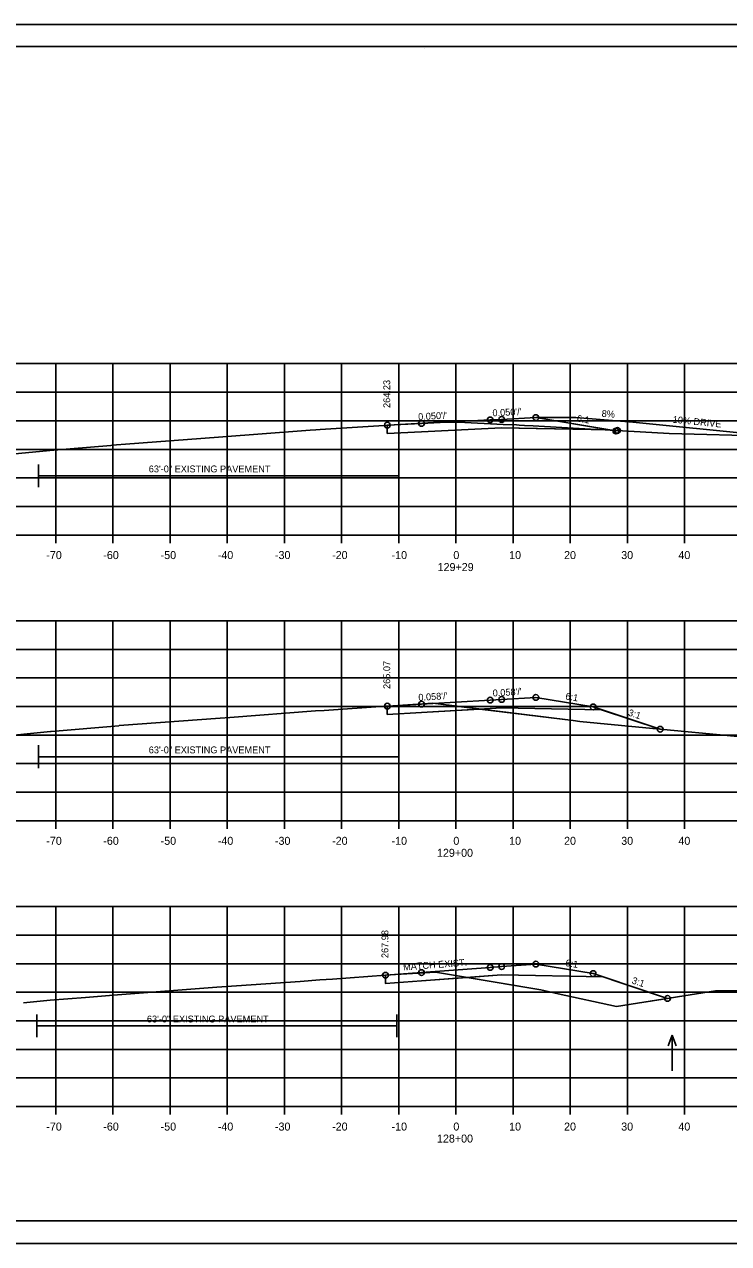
# Model space of a CAD drawing. Extents: x 1103485 to 1107180, y 2010593 to 2011873.
# Drawn here: x 1106941.7 to 1107064.9, y 2011019.5 to 2011232.8 of the extents above; entities that cross this region are included whole.
import ezdxf

# ---------------------------------------------------------------- set-up
doc = ezdxf.new("R2010")
doc.units = 0
for name, color, linetype in [('R_Alt Surface', 7, 'Continuous'), ('R_Axis', 7, 'Continuous'), ('R_Axis Annot', 7, 'Continuous'), ('R_Border', 7, 'Continuous'), ('R_Contours', 7, 'Continuous'), ('R_Dimension', 7, 'Continuous'), ('R_Drive', 7, 'Continuous'), ('R_Exist Surface', 7, 'Continuous'), ('R_Fin Surface', 7, 'Continuous'), ('R_Grid', 7, 'Continuous'), ('R_No Plot', 7, 'Continuous'), ('R_Proposed Const Limits', 7, 'Continuous'), ('R_Water Annot', 7, 'Continuous'), ('R_Xsect Elev', 7, 'Continuous'), ('R_Xsect Slope', 7, 'Continuous')]:
    doc.layers.add(name, color=color, linetype=linetype)

msp = doc.modelspace()

# ---------------------------------------------------------------- linework, layer by layer
at = {"layer": 'R_Alt Surface'}
for points in [[(1107005.18, 2011162.73), (1107005.18, 2011161.27), (1107011.18, 2011161.57), (1107025.18, 2011162.27), (1107044.02, 2011161.9)], [(1107005.18, 2011113.56), (1107005.18, 2011112.1), (1107011.18, 2011112.45), (1107025.18, 2011113.27), (1107042.67, 2011112.92)], [(1107004.86, 2011066.47), (1107004.86, 2011065.01), (1107011.18, 2011065.48), (1107025.18, 2011066.52), (1107042.97, 2011066.17)]]:
    msp.add_lwpolyline(points, dxfattribs=at)
at = {"layer": 'R_Axis'}
for p, q in [((1106867.18, 2011143.49), (1107167.18, 2011143.49)), ((1106947.18, 2011142.09), (1106947.18, 2011143.49)), ((1106957.18, 2011142.09), (1106957.18, 2011143.49)), ((1106967.18, 2011142.09), (1106967.18, 2011143.49)), ((1106977.18, 2011142.09), (1106977.18, 2011143.49)), ((1106987.18, 2011142.09), (1106987.18, 2011143.49)), ((1106997.18, 2011142.09), (1106997.18, 2011143.49)), ((1107007.18, 2011142.09), (1107007.18, 2011143.49)), ((1107017.18, 2011142.09), (1107017.18, 2011143.49)), ((1107027.18, 2011142.09), (1107027.18, 2011143.49)), ((1107037.18, 2011142.09), (1107037.18, 2011143.49)), ((1107047.18, 2011142.09), (1107047.18, 2011143.49)), ((1107057.18, 2011142.09), (1107057.18, 2011143.49)), ((1106867.18, 2011093.49), (1107167.18, 2011093.49)), ((1106947.18, 2011092.09), (1106947.18, 2011093.49)), ((1106957.18, 2011092.09), (1106957.18, 2011093.49)), ((1106967.18, 2011092.09), (1106967.18, 2011093.49)), ((1106977.18, 2011092.09), (1106977.18, 2011093.49)), ((1106987.18, 2011092.09), (1106987.18, 2011093.49)), ((1106997.18, 2011092.09), (1106997.18, 2011093.49)), ((1107007.18, 2011092.09), (1107007.18, 2011093.49)), ((1107017.18, 2011092.09), (1107017.18, 2011093.49)), ((1107027.18, 2011092.09), (1107027.18, 2011093.49)), ((1107037.18, 2011092.09), (1107037.18, 2011093.49)), ((1107047.18, 2011092.09), (1107047.18, 2011093.49)), ((1107057.18, 2011092.09), (1107057.18, 2011093.49)), ((1106867.18, 2011043.49), (1107167.18, 2011043.49)), ((1106947.18, 2011042.09), (1106947.18, 2011043.49)), ((1106957.18, 2011042.09), (1106957.18, 2011043.49)), ((1106967.18, 2011042.09), (1106967.18, 2011043.49)), ((1106977.18, 2011042.09), (1106977.18, 2011043.49)), ((1106987.18, 2011042.09), (1106987.18, 2011043.49)), ((1106997.18, 2011042.09), (1106997.18, 2011043.49)), ((1107007.18, 2011042.09), (1107007.18, 2011043.49)), ((1107017.18, 2011042.09), (1107017.18, 2011043.49)), ((1107027.18, 2011042.09), (1107027.18, 2011043.49)), ((1107037.18, 2011042.09), (1107037.18, 2011043.49)), ((1107047.18, 2011042.09), (1107047.18, 2011043.49)), ((1107057.18, 2011042.09), (1107057.18, 2011043.49))]:
    msp.add_line(p, q, dxfattribs=at)
at = {"layer": 'R_Border'}
for p, q in [((1106859.18, 2011228.95), (1107175.36, 2011228.95)), ((1107011.7, 2011228.69), (1107011.7, 2011228.69)), ((1107011.7, 2011228.69), (1107011.7, 2011228.69)), ((1107175.36, 2011023.49), (1106859.18, 2011023.49))]:
    msp.add_line(p, q, dxfattribs=at)
at = {"layer": 'R_Contours'}
for points in [[(1107005.18, 2011162.72), (1107006.43, 2011162.79), (1107013.24, 2011163.17), (1107017.63, 2011163.22), (1107025.43, 2011162.86), (1107027.78, 2011162.8), (1107028.26, 2011162.74), (1107029.15, 2011162.68), (1107030.69, 2011162.62), (1107040.74, 2011162.01), (1107043.32, 2011161.91), (1107044.02, 2011161.88), (1107031.21, 2011162.15), (1107025.18, 2011162.27), (1107011.18, 2011161.57), (1107005.18, 2011161.27)], [(1107044.02, 2011161.88), (1107044.22, 2011161.86), (1107044.02, 2011161.9)], [(1107044.22, 2011161.86), (1107045.46, 2011161.79), (1107045.18, 2011161.7), (1107044.75, 2011161.78)], [(1107005.18, 2011113.56), (1107006.15, 2011113.62), (1107013.13, 2011114.06), (1107021.35, 2011113.05), (1107011.18, 2011112.45), (1107005.18, 2011112.1)], [(1107021.35, 2011113.05), (1107037.71, 2011111.04), (1107038.87, 2011110.88), (1107049.2, 2011109.86), (1107052.91, 2011109.51), (1107042.67, 2011112.92), (1107025.18, 2011113.27)], [(1107004.86, 2011066.47), (1107006.62, 2011066.58), (1107013.6, 2011066.99), (1107017.82, 2011066.3), (1107019.17, 2011066.07), (1107011.18, 2011065.48), (1107004.86, 2011065.01)], [(1107019.17, 2011066.07), (1107032.05, 2011063.91), (1107035.04, 2011063.23), (1107045.3, 2011061), (1107048.96, 2011061.59), (1107054.21, 2011062.42), (1107047.95, 2011064.51), (1107042.97, 2011066.17), (1107025.18, 2011066.52)]]:
    msp.add_lwpolyline(points, close=True, dxfattribs=at)
at = {"layer": 'R_Dimension'}
for p, q in [((1106944.18, 2011155.86), (1106944.18, 2011151.86)), ((1107007.18, 2011155.86), (1107007.18, 2011151.86)), ((1106944.18, 2011153.86), (1107007.18, 2011153.86)), ((1106944.18, 2011106.7), (1106944.18, 2011102.7)), ((1107007.18, 2011106.7), (1107007.18, 2011102.7)), ((1106944.18, 2011104.7), (1107007.18, 2011104.7)), ((1106943.86, 2011059.61), (1106943.86, 2011055.61)), ((1107006.86, 2011059.61), (1107006.86, 2011055.61)), ((1106943.86, 2011057.61), (1107006.86, 2011057.61))]:
    msp.add_line(p, q, dxfattribs=at)
at = {"layer": 'R_Drive'}
for p, q in [((1107031.18, 2011164.04), (1107038.18, 2011164.04)), ((1107038.18, 2011164.04), (1107048.15, 2011163.24)), ((1107048.15, 2011163.24), (1107072.23, 2011160.83))]:
    msp.add_line(p, q, dxfattribs=at)
at = {"layer": 'R_Exist Surface'}
for points in [[(1106938.22, 2011157.52), (1106946.11, 2011158.31), (1106956.82, 2011159.19), (1106957.82, 2011159.27), (1106959.37, 2011159.39), (1106975.66, 2011160.62), (1106991.69, 2011161.82), (1106992.7, 2011161.9), (1106993.41, 2011161.94), (1107004.6, 2011162.68), (1107006.43, 2011162.79), (1107013.24, 2011163.17), (1107017.63, 2011163.22), (1107025.43, 2011162.86), (1107027.78, 2011162.8), (1107028.26, 2011162.74), (1107029.15, 2011162.68), (1107030.69, 2011162.62), (1107040.74, 2011162.01), (1107043.32, 2011161.91), (1107054.5, 2011161.29), (1107061.07, 2011161.07), (1107069.8, 2011160.88)], [(1106937.63, 2011108.24), (1106942.74, 2011108.76), (1106946.24, 2011109.13), (1106946.39, 2011109.14), (1106958.19, 2011110.13), (1106958.28, 2011110.14), (1106975.96, 2011111.43), (1106977.65, 2011111.56), (1106992.62, 2011112.71), (1106994.11, 2011112.81), (1107004.78, 2011113.53), (1107006.15, 2011113.62), (1107013.13, 2011114.06), (1107037.71, 2011111.04), (1107038.87, 2011110.88), (1107049.2, 2011109.86), (1107068.93, 2011108)], [(1106941.53, 2011061.65), (1106946.2, 2011062.1), (1106952.39, 2011062.6), (1106957.95, 2011063.05), (1106970.83, 2011064.03), (1106975.36, 2011064.36), (1106989.92, 2011065.4), (1106993.4, 2011065.64), (1106995.57, 2011065.79), (1107004.86, 2011066.47), (1107006.62, 2011066.58), (1107013.6, 2011066.99), (1107017.82, 2011066.3), (1107032.05, 2011063.91), (1107035.04, 2011063.23), (1107045.3, 2011061), (1107048.96, 2011061.59), (1107062.61, 2011063.75), (1107064.02, 2011063.76), (1107073.65, 2011063.89)]]:
    msp.add_lwpolyline(points, dxfattribs=at)
at = {"layer": 'R_Fin Surface'}
for points in [[(1107005.18, 2011162.73), (1107011.18, 2011163.03), (1107023.18, 2011163.63), (1107025.18, 2011163.73), (1107031.18, 2011164.04)], [(1107005.18, 2011162.73), (1107011.18, 2011163.03), (1107023.18, 2011163.63), (1107025.18, 2011163.73), (1107031.18, 2011164.04), (1107044.02, 2011161.9), (1107045.18, 2011161.7), (1107045.46, 2011161.79)], [(1107005.18, 2011113.56), (1107011.18, 2011113.91), (1107023.18, 2011114.62), (1107025.18, 2011114.73), (1107031.18, 2011115.08), (1107041.18, 2011113.42), (1107042.67, 2011112.92), (1107052.91, 2011109.51)], [(1107005.18, 2011113.56), (1107011.18, 2011113.91), (1107023.18, 2011114.62), (1107025.18, 2011114.73), (1107031.18, 2011115.08)], [(1107004.86, 2011066.47), (1107011.18, 2011066.94), (1107023.18, 2011067.83), (1107025.18, 2011067.98), (1107031.18, 2011068.43), (1107041.18, 2011066.76), (1107042.97, 2011066.17), (1107054.21, 2011062.42)], [(1107004.86, 2011066.47), (1107011.18, 2011066.94), (1107023.18, 2011067.83), (1107025.18, 2011067.98), (1107031.18, 2011068.43)]]:
    msp.add_lwpolyline(points, dxfattribs=at)
at = {"layer": 'R_Grid'}
for p, q in [((1106867.18, 2011173.49), (1107167.18, 2011173.49)), ((1106947.18, 2011143.49), (1106947.18, 2011173.49)), ((1106957.18, 2011143.49), (1106957.18, 2011173.49)), ((1106967.18, 2011143.49), (1106967.18, 2011173.49)), ((1106977.18, 2011143.49), (1106977.18, 2011173.49)), ((1106987.18, 2011143.49), (1106987.18, 2011173.49)), ((1106997.18, 2011143.49), (1106997.18, 2011173.49)), ((1107007.18, 2011143.49), (1107007.18, 2011173.49)), ((1107017.18, 2011143.49), (1107017.18, 2011173.49)), ((1107027.18, 2011143.49), (1107027.18, 2011173.49)), ((1107037.18, 2011143.49), (1107037.18, 2011173.49)), ((1107047.18, 2011143.49), (1107047.18, 2011173.49)), ((1107057.18, 2011143.49), (1107057.18, 2011173.49)), ((1106867.18, 2011168.49), (1107167.18, 2011168.49)), ((1106867.18, 2011163.49), (1107167.18, 2011163.49)), ((1106867.18, 2011158.49), (1107167.18, 2011158.49)), ((1106867.18, 2011153.49), (1107167.18, 2011153.49)), ((1106867.18, 2011148.49), (1107167.18, 2011148.49)), ((1106867.18, 2011143.49), (1107167.18, 2011143.49)), ((1106867.18, 2011128.49), (1107167.18, 2011128.49)), ((1106947.18, 2011093.49), (1106947.18, 2011128.49)), ((1106957.18, 2011093.49), (1106957.18, 2011128.49)), ((1106967.18, 2011093.49), (1106967.18, 2011128.49)), ((1106977.18, 2011093.49), (1106977.18, 2011128.49)), ((1106987.18, 2011093.49), (1106987.18, 2011128.49)), ((1106997.18, 2011093.49), (1106997.18, 2011128.49)), ((1107007.18, 2011093.49), (1107007.18, 2011128.49)), ((1107017.18, 2011093.49), (1107017.18, 2011128.49)), ((1107027.18, 2011093.49), (1107027.18, 2011128.49)), ((1107037.18, 2011093.49), (1107037.18, 2011128.49)), ((1107047.18, 2011093.49), (1107047.18, 2011128.49)), ((1107057.18, 2011093.49), (1107057.18, 2011128.49)), ((1106867.18, 2011123.49), (1107167.18, 2011123.49)), ((1106867.18, 2011118.49), (1107167.18, 2011118.49)), ((1106867.18, 2011113.49), (1107167.18, 2011113.49)), ((1106867.18, 2011108.49), (1107167.18, 2011108.49)), ((1106867.18, 2011103.49), (1107167.18, 2011103.49)), ((1106867.18, 2011098.49), (1107167.18, 2011098.49)), ((1106867.18, 2011093.49), (1107167.18, 2011093.49)), ((1106867.18, 2011078.49), (1107167.18, 2011078.49)), ((1106947.18, 2011043.49), (1106947.18, 2011078.49)), ((1106957.18, 2011043.49), (1106957.18, 2011078.49)), ((1106967.18, 2011043.49), (1106967.18, 2011078.49)), ((1106977.18, 2011043.49), (1106977.18, 2011078.49)), ((1106987.18, 2011043.49), (1106987.18, 2011078.49)), ((1106997.18, 2011043.49), (1106997.18, 2011078.49)), ((1107007.18, 2011043.49), (1107007.18, 2011078.49)), ((1107017.18, 2011043.49), (1107017.18, 2011078.49)), ((1107027.18, 2011043.49), (1107027.18, 2011078.49)), ((1107037.18, 2011043.49), (1107037.18, 2011078.49)), ((1107047.18, 2011043.49), (1107047.18, 2011078.49)), ((1107057.18, 2011043.49), (1107057.18, 2011078.49)), ((1106867.18, 2011073.49), (1107167.18, 2011073.49)), ((1106867.18, 2011068.49), (1107167.18, 2011068.49)), ((1106867.18, 2011063.49), (1107167.18, 2011063.49)), ((1106867.18, 2011058.49), (1107167.18, 2011058.49)), ((1106867.18, 2011053.49), (1107167.18, 2011053.49)), ((1106867.18, 2011048.49), (1107167.18, 2011048.49)), ((1106867.18, 2011043.49), (1107167.18, 2011043.49))]:
    msp.add_line(p, q, dxfattribs=at)
at = {"layer": 'R_No Plot'}
for p, q in [((1106846.78, 2011232.85), (1107180.12, 2011232.85)), ((1106846.78, 2011019.51), (1107180.12, 2011019.51))]:
    msp.add_line(p, q, dxfattribs=at)
for points in [[(1106846.78, 2011232.85), (1107180.12, 2011232.85), (1107180.12, 2011019.51), (1106846.78, 2011019.51)], [(1107093.1, 2011228.95), (1107093.1, 2011219.07), (1107128.84, 2011219.07), (1107128.84, 2011216.15), (1107152.04, 2011216.15), (1107152.04, 2011191.82), (1107175.36, 2011191.82), (1107175.36, 2011023.49), (1106859.18, 2011023.49), (1106859.18, 2011228.95)]]:
    msp.add_lwpolyline(points, close=True, dxfattribs=at)
for centre in [(1107011.18, 2011163.03), (1107023.18, 2011163.63), (1107025.18, 2011163.73), (1107031.18, 2011164.04), (1107005.18, 2011162.73), (1107045.18, 2011161.7), (1107045.46, 2011161.79), (1107045.46, 2011161.79), (1107011.18, 2011113.91), (1107023.18, 2011114.62), (1107025.18, 2011114.73), (1107031.18, 2011115.08), (1107005.18, 2011113.56), (1107041.18, 2011113.42), (1107052.91, 2011109.51), (1107011.18, 2011066.94), (1107023.18, 2011067.83), (1107025.18, 2011067.98), (1107031.18, 2011068.43), (1107004.86, 2011066.47), (1107041.18, 2011066.76), (1107054.21, 2011062.42)]:
    msp.add_circle(centre, 0.5, dxfattribs=at)
at = {"layer": 'R_Proposed Const Limits'}
for points in [[(1107031.18, 2011164.04), (1107045.18, 2011161.7), (1107045.46, 2011161.79)], [(1107031.18, 2011115.08), (1107041.18, 2011113.42), (1107052.91, 2011109.51)], [(1107031.18, 2011068.43), (1107041.18, 2011066.76), (1107054.21, 2011062.42)]]:
    msp.add_lwpolyline(points, dxfattribs=at)
at = {"layer": 'R_Water Annot'}
for p, q in [((1107055.01, 2011056.01), (1107054.31, 2011054.09)), ((1107055.01, 2011049.72), (1107055.01, 2011056.01)), ((1107055.01, 2011056.01), (1107055.71, 2011054.09))]:
    msp.add_line(p, q, dxfattribs=at)

# ---------------------------------------------------------------- texts
at = {"layer": 'R_Axis Annot'}
for s, p in [('-70', (1106945.52, 2011139.29)), ('-60', (1106955.49, 2011139.29)), ('-50', (1106965.52, 2011139.29)), ('-40', (1106975.52, 2011139.29)), ('-30', (1106985.52, 2011139.29)), ('-20', (1106995.52, 2011139.29)), ('-10', (1107005.92, 2011139.29)), ('0', (1107016.73, 2011139.29)), ('10', (1107026.49, 2011139.29)), ('20', (1107036.1, 2011139.29)), ('30', (1107046.1, 2011139.29)), ('40', (1107056.1, 2011139.29)), ('129+29', (1107013.98, 2011137.19)), ('-70', (1106945.52, 2011089.29)), ('-60', (1106955.49, 2011089.29)), ('-50', (1106965.52, 2011089.29)), ('-40', (1106975.52, 2011089.29)), ('-30', (1106985.52, 2011089.29)), ('-20', (1106995.52, 2011089.29)), ('-10', (1107005.92, 2011089.29)), ('0', (1107016.73, 2011089.29)), ('10', (1107026.49, 2011089.29)), ('20', (1107036.1, 2011089.29)), ('30', (1107046.1, 2011089.29)), ('40', (1107056.1, 2011089.29)), ('129+00', (1107013.87, 2011087.19)), ('-70', (1106945.52, 2011039.29)), ('-60', (1106955.49, 2011039.29)), ('-50', (1106965.52, 2011039.29)), ('-40', (1106975.52, 2011039.29)), ('-30', (1106985.52, 2011039.29)), ('-20', (1106995.52, 2011039.29)), ('-10', (1107005.92, 2011039.29)), ('0', (1107016.73, 2011039.29)), ('10', (1107026.49, 2011039.29)), ('20', (1107036.1, 2011039.29)), ('30', (1107046.1, 2011039.29)), ('40', (1107056.1, 2011039.29)), ('128+00', (1107013.87, 2011037.19))]:
    msp.add_text(s, height=1.4, dxfattribs=at).set_placement(p)
at = {"layer": 'R_Dimension'}
for p in [(1106963.44, 2011154.46), (1106963.44, 2011105.3), (1106963.12, 2011058.21)]:
    msp.add_text('63\'-0" EXISTING PAVEMENT', height=1.2, dxfattribs=at).set_placement(p)
at = {"layer": 'R_Drive'}
for s, rotation, p in [('8%', 355.426, (1107042.64, 2011164.19)), ('10% DRIVE', 354.289, (1107055.06, 2011163.15))]:
    msp.add_text(s, height=1.2, rotation=rotation, dxfattribs=at).set_placement(p)
at = {"layer": 'R_Xsect Elev'}
for s, p in [('264.23', (1107005.68, 2011165.73)), ('265.07', (1107005.68, 2011116.56)), ('267.98', (1107005.36, 2011069.47))]:
    msp.add_text(s, height=1.2, rotation=90, dxfattribs=at).set_placement(p)
at = {"layer": 'R_Xsect Slope'}
for s, rotation, p in [("0.050'/'", 2.8851, (1107023.6, 2011164.26)), ("0.050'/'", 2.8847, (1107010.6, 2011163.6)), ('6:1', 350.5358, (1107038.27, 2011163.36)), ("0.058'/'", 3.3458, (1107023.64, 2011115.24)), ("0.058'/'", 3.3455, (1107010.64, 2011114.48)), ('6:1', 350.5358, (1107036.27, 2011114.74)), ('3:1', 341.5668, (1107047.2, 2011111.94)), ('MATCH EXIST.', 4.257, (1107007.98, 2011067.3)), ('6:1', 350.5358, (1107036.27, 2011068.09)), ('3:1', 341.5668, (1107047.85, 2011065.07))]:
    msp.add_text(s, height=1.2, rotation=rotation, dxfattribs=at).set_placement(p)

doc.saveas('drawing.dxf')
